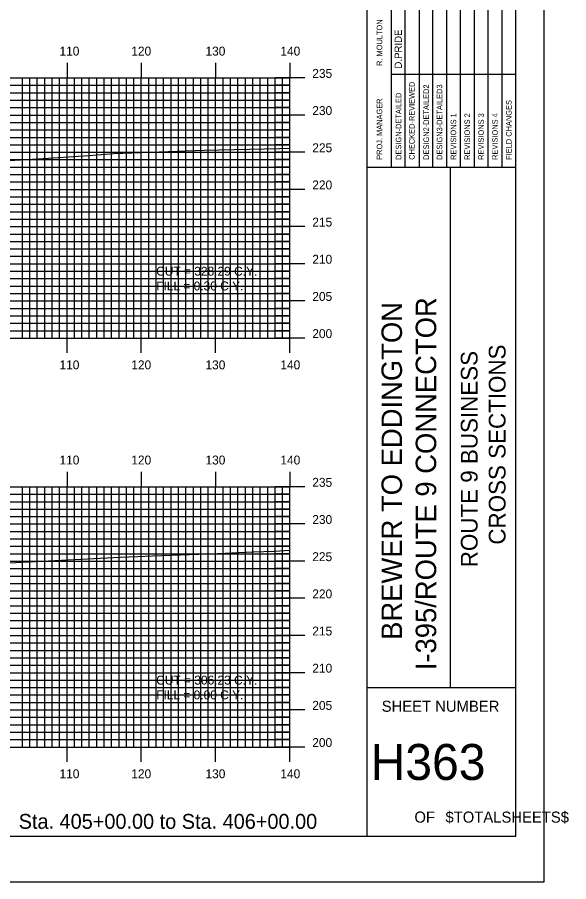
# Model space of a CAD drawing. Extents: x 851742 to 852085, y 364785 to 365005.
# Drawn here: x 852011 to 852085.2, y 364785.1 to 364901.4 of the extents above; entities that cross this region are included whole.
import ezdxf

# ---------------------------------------------------------------- set-up
doc = ezdxf.new("R2010")
doc.units = 0
for name, color, linetype in [('BORDER', 7, 'Continuous'), ('D_Text_Standard', 7, 'Continuous'), ('H_V ANNOTATION', 7, 'Continuous'), ('MAJOR', 7, 'Continuous'), ('MINOR', 7, 'Continuous'), ('PLOT BOUNDARY', 7, 'Continuous'), ('S_Roadway_Centerline', 7, 'Continuous')]:
    doc.layers.add(name, color=color, linetype=linetype)

msp = doc.modelspace()

# ---------------------------------------------------------------- linework, layer by layer
at = {"layer": 'BORDER'}
for p, q in [((852058.1, 364791.23), (852058.1, 365001.23)), ((852058.1, 364881.24), (852078.1, 364881.24)), ((852069.29, 364811.24), (852069.29, 364881.24)), ((852058.1, 364811.24), (852078.1, 364811.24))]:
    msp.add_line(p, q, dxfattribs=at)
msp.add_lwpolyline([(851758.1, 364791.23), (852078.1, 364791.23), (852078.1, 365001.23), (851758.1, 365001.23)], close=True, dxfattribs=at)
for points in [[(852063.2, 364881.24), (852063.2, 364916.24)], [(852065.06, 364916.24), (852065.06, 364881.24)], [(852066.93, 364881.24), (852066.93, 364916.24)], [(852068.79, 364881.24), (852068.79, 364916.24)], [(852070.65, 364881.24), (852070.65, 364916.24)], [(852072.52, 364881.24), (852072.52, 364916.24)], [(852074.38, 364881.24), (852074.38, 364916.24)], [(852076.24, 364881.24), (852076.24, 364916.24)], [(852061.34, 364881.24), (852061.34, 364914.83)], [(852061.33, 364893.74), (852078.1, 364893.74)]]:
    msp.add_lwpolyline(points, dxfattribs=at)
at = {"layer": 'MAJOR'}
for p, q in [((852017.7, 364895.24), (852017.7, 364893.23)), ((852027.7, 364895.24), (852027.7, 364893.23)), ((852037.7, 364895.24), (852037.7, 364893.23)), ((852047.7, 364895.24), (852047.7, 364893.23)), ((851767.7, 364893.23), (852047.7, 364893.23)), ((851767.7, 364893.23), (852047.7, 364893.23)), ((852017.7, 364858.23), (852017.7, 364893.23)), ((852027.7, 364858.23), (852027.7, 364893.23)), ((852037.7, 364858.23), (852037.7, 364893.23)), ((852049.71, 364893.23), (852045.7, 364893.23)), ((852047.7, 364858.23), (852047.7, 364893.23)), ((852047.7, 364858.23), (852047.7, 364893.23)), ((851767.7, 364888.23), (852047.7, 364888.23)), ((852049.71, 364888.23), (852045.7, 364888.23)), ((851767.7, 364883.23), (852047.7, 364883.23)), ((852049.71, 364883.23), (852045.7, 364883.23)), ((851767.7, 364878.23), (852047.7, 364878.23)), ((852049.71, 364878.23), (852045.7, 364878.23)), ((851767.7, 364873.23), (852047.7, 364873.23)), ((852049.71, 364873.23), (852045.7, 364873.23)), ((851767.7, 364868.23), (852047.7, 364868.23)), ((852049.71, 364868.23), (852045.7, 364868.23)), ((851767.7, 364863.23), (852047.7, 364863.23)), ((852049.71, 364863.23), (852045.7, 364863.23)), ((851767.7, 364858.23), (852047.7, 364858.23)), ((851767.7, 364858.23), (852047.7, 364858.23)), ((852017.7, 364856.23), (852017.7, 364858.23)), ((852027.7, 364856.23), (852027.7, 364858.23)), ((852037.7, 364856.23), (852037.7, 364858.23)), ((852049.71, 364858.23), (852045.7, 364858.23)), ((852047.7, 364856.23), (852047.7, 364858.23)), ((852017.7, 364840.24), (852017.7, 364838.23)), ((852027.7, 364840.24), (852027.7, 364838.23)), ((852037.7, 364840.24), (852037.7, 364838.23)), ((852047.7, 364840.24), (852047.7, 364838.23)), ((851767.7, 364838.23), (852047.7, 364838.23)), ((851767.7, 364838.23), (852047.7, 364838.23)), ((852017.7, 364803.23), (852017.7, 364838.23)), ((852027.7, 364803.23), (852027.7, 364838.23)), ((852037.7, 364803.23), (852037.7, 364838.23)), ((852049.71, 364838.23), (852045.7, 364838.23)), ((852047.7, 364803.23), (852047.7, 364838.23)), ((852047.7, 364803.23), (852047.7, 364838.23)), ((851767.7, 364833.23), (852047.7, 364833.23)), ((852049.71, 364833.23), (852045.7, 364833.23)), ((851767.7, 364828.23), (852047.7, 364828.23)), ((852049.71, 364828.23), (852045.7, 364828.23)), ((851767.7, 364823.23), (852047.7, 364823.23)), ((852049.71, 364823.23), (852045.7, 364823.23)), ((851767.7, 364818.23), (852047.7, 364818.23)), ((852049.71, 364818.23), (852045.7, 364818.23)), ((851767.7, 364813.23), (852047.7, 364813.23)), ((852049.71, 364813.23), (852045.7, 364813.23)), ((851767.7, 364808.23), (852047.7, 364808.23)), ((852049.71, 364808.23), (852045.7, 364808.23)), ((851767.7, 364803.23), (852047.7, 364803.23)), ((851767.7, 364803.23), (852047.7, 364803.23)), ((852017.7, 364801.23), (852017.7, 364803.23)), ((852027.7, 364801.23), (852027.7, 364803.23)), ((852037.7, 364801.23), (852037.7, 364803.23)), ((852049.71, 364803.23), (852045.7, 364803.23)), ((852047.7, 364801.23), (852047.7, 364803.23))]:
    msp.add_line(p, q, dxfattribs=at)
at = {"layer": 'MINOR'}
for p, q in [((852011.7, 364858.23), (852011.7, 364893.23)), ((852012.7, 364858.23), (852012.7, 364893.23)), ((852013.7, 364858.23), (852013.7, 364893.23)), ((852014.7, 364858.23), (852014.7, 364893.23)), ((852015.7, 364858.23), (852015.7, 364893.23)), ((852016.7, 364858.23), (852016.7, 364893.23)), ((852018.7, 364858.23), (852018.7, 364893.23)), ((852019.7, 364858.23), (852019.7, 364893.23)), ((852020.7, 364858.23), (852020.7, 364893.23)), ((852021.7, 364858.23), (852021.7, 364893.23)), ((852022.7, 364858.23), (852022.7, 364893.23)), ((852023.7, 364858.23), (852023.7, 364893.23)), ((852024.7, 364858.23), (852024.7, 364893.23)), ((852025.7, 364858.23), (852025.7, 364893.23)), ((852026.7, 364858.23), (852026.7, 364893.23)), ((852028.7, 364858.23), (852028.7, 364893.23)), ((852029.7, 364858.23), (852029.7, 364893.23)), ((852030.7, 364858.23), (852030.7, 364893.23)), ((852031.7, 364858.23), (852031.7, 364893.23)), ((852032.7, 364858.23), (852032.7, 364893.23)), ((852033.7, 364858.23), (852033.7, 364893.23)), ((852034.7, 364858.23), (852034.7, 364893.23)), ((852035.7, 364858.23), (852035.7, 364893.23)), ((852036.7, 364858.23), (852036.7, 364893.23)), ((852038.7, 364858.23), (852038.7, 364893.23)), ((852039.7, 364858.23), (852039.7, 364893.23)), ((852040.7, 364858.23), (852040.7, 364893.23)), ((852041.7, 364858.23), (852041.7, 364893.23)), ((852042.7, 364858.23), (852042.7, 364893.23)), ((852043.7, 364858.23), (852043.7, 364893.23)), ((852044.7, 364858.23), (852044.7, 364893.23)), ((852045.7, 364858.23), (852045.7, 364893.23)), ((852046.7, 364858.23), (852046.7, 364893.23)), ((851767.7, 364892.23), (852047.7, 364892.23)), ((852047.7, 364892.23), (852045.7, 364892.23)), ((851767.7, 364891.23), (852047.7, 364891.23)), ((852047.7, 364891.23), (852045.7, 364891.23)), ((851767.7, 364890.23), (852047.7, 364890.23)), ((852047.7, 364890.23), (852045.7, 364890.23)), ((851767.7, 364889.23), (852047.7, 364889.23)), ((852047.7, 364889.23), (852045.7, 364889.23)), ((851767.7, 364887.23), (852047.7, 364887.23)), ((852047.7, 364887.23), (852045.7, 364887.23)), ((851767.7, 364886.23), (852047.7, 364886.23)), ((852047.7, 364886.23), (852045.7, 364886.23)), ((851767.7, 364885.23), (852047.7, 364885.23)), ((852047.7, 364885.23), (852045.7, 364885.23)), ((851767.7, 364884.23), (852047.7, 364884.23)), ((852047.7, 364884.23), (852045.7, 364884.23)), ((851767.7, 364882.23), (852047.7, 364882.23)), ((851767.7, 364881.23), (852047.7, 364881.23)), ((852047.7, 364882.23), (852045.7, 364882.23)), ((852047.7, 364881.23), (852045.7, 364881.23)), ((851767.7, 364880.23), (852047.7, 364880.23)), ((852047.7, 364880.23), (852045.7, 364880.23)), ((851767.7, 364879.23), (852047.7, 364879.23)), ((852047.7, 364879.23), (852045.7, 364879.23)), ((851767.7, 364877.23), (852047.7, 364877.23)), ((852047.7, 364877.23), (852045.7, 364877.23)), ((851767.7, 364876.23), (852047.7, 364876.23)), ((852047.7, 364876.23), (852045.7, 364876.23)), ((851767.7, 364875.23), (852047.7, 364875.23)), ((851767.7, 364874.23), (852047.7, 364874.23)), ((852047.7, 364875.23), (852045.7, 364875.23)), ((852047.7, 364874.23), (852045.7, 364874.23)), ((851767.7, 364872.23), (852047.7, 364872.23)), ((852047.7, 364872.23), (852045.7, 364872.23)), ((851767.7, 364871.23), (852047.7, 364871.23)), ((852047.7, 364871.23), (852045.7, 364871.23)), ((851767.7, 364870.23), (852047.7, 364870.23)), ((852047.7, 364870.23), (852045.7, 364870.23)), ((851767.7, 364869.23), (852047.7, 364869.23)), ((852047.7, 364869.23), (852045.7, 364869.23)), ((851767.7, 364867.23), (852047.7, 364867.23)), ((852047.7, 364867.23), (852045.7, 364867.23)), ((851767.7, 364866.23), (852047.7, 364866.23)), ((852047.7, 364866.23), (852045.7, 364866.23)), ((851767.7, 364865.23), (852047.7, 364865.23)), ((852047.7, 364865.23), (852045.7, 364865.23)), ((851767.7, 364864.23), (852047.7, 364864.23)), ((852047.7, 364864.23), (852045.7, 364864.23)), ((851767.7, 364862.23), (852047.7, 364862.23)), ((852047.7, 364862.23), (852045.7, 364862.23)), ((851767.7, 364861.23), (852047.7, 364861.23)), ((851767.7, 364860.23), (852047.7, 364860.23)), ((852047.7, 364861.23), (852045.7, 364861.23)), ((852047.7, 364860.23), (852045.7, 364860.23)), ((851767.7, 364859.23), (852047.7, 364859.23)), ((852047.7, 364859.23), (852045.7, 364859.23)), ((852011.7, 364803.23), (852011.7, 364838.23)), ((852012.7, 364803.23), (852012.7, 364838.23)), ((852013.7, 364803.23), (852013.7, 364838.23)), ((852014.7, 364803.23), (852014.7, 364838.23)), ((852015.7, 364803.23), (852015.7, 364838.23)), ((852016.7, 364803.23), (852016.7, 364838.23)), ((852018.7, 364803.23), (852018.7, 364838.23)), ((852019.7, 364803.23), (852019.7, 364838.23)), ((852020.7, 364803.23), (852020.7, 364838.23)), ((852021.7, 364803.23), (852021.7, 364838.23)), ((852022.7, 364803.23), (852022.7, 364838.23)), ((852023.7, 364803.23), (852023.7, 364838.23)), ((852024.7, 364803.23), (852024.7, 364838.23)), ((852025.7, 364803.23), (852025.7, 364838.23)), ((852026.7, 364803.23), (852026.7, 364838.23)), ((852028.7, 364803.23), (852028.7, 364838.23)), ((852029.7, 364803.23), (852029.7, 364838.23)), ((852030.7, 364803.23), (852030.7, 364838.23)), ((852031.7, 364803.23), (852031.7, 364838.23)), ((852032.7, 364803.23), (852032.7, 364838.23)), ((852033.7, 364803.23), (852033.7, 364838.23)), ((852034.7, 364803.23), (852034.7, 364838.23)), ((852035.7, 364803.23), (852035.7, 364838.23)), ((852036.7, 364803.23), (852036.7, 364838.23)), ((852038.7, 364803.23), (852038.7, 364838.23)), ((852039.7, 364803.23), (852039.7, 364838.23)), ((852040.7, 364803.23), (852040.7, 364838.23)), ((852041.7, 364803.23), (852041.7, 364838.23)), ((852042.7, 364803.23), (852042.7, 364838.23)), ((852043.7, 364803.23), (852043.7, 364838.23)), ((852044.7, 364803.23), (852044.7, 364838.23)), ((852045.7, 364803.23), (852045.7, 364838.23)), ((852046.7, 364803.23), (852046.7, 364838.23)), ((851767.7, 364837.23), (852047.7, 364837.23)), ((852047.7, 364837.23), (852045.7, 364837.23)), ((851767.7, 364836.23), (852047.7, 364836.23)), ((852047.7, 364836.23), (852045.7, 364836.23)), ((851767.7, 364835.23), (852047.7, 364835.23)), ((852047.7, 364835.23), (852045.7, 364835.23)), ((851767.7, 364834.23), (852047.7, 364834.23)), ((852047.7, 364834.23), (852045.7, 364834.23)), ((851767.7, 364832.23), (852047.7, 364832.23)), ((851767.7, 364831.23), (852047.7, 364831.23)), ((852047.7, 364832.23), (852045.7, 364832.23)), ((852047.7, 364831.23), (852045.7, 364831.23)), ((851767.7, 364830.23), (852047.7, 364830.23)), ((852047.7, 364830.23), (852045.7, 364830.23)), ((851767.7, 364829.23), (852047.7, 364829.23)), ((852047.7, 364829.23), (852045.7, 364829.23)), ((851767.7, 364827.23), (852047.7, 364827.23)), ((852047.7, 364827.23), (852045.7, 364827.23)), ((851767.7, 364826.23), (852047.7, 364826.23)), ((852047.7, 364826.23), (852045.7, 364826.23)), ((851767.7, 364825.23), (852047.7, 364825.23)), ((851767.7, 364824.23), (852047.7, 364824.23)), ((852047.7, 364825.23), (852045.7, 364825.23)), ((852047.7, 364824.23), (852045.7, 364824.23)), ((851767.7, 364822.23), (852047.7, 364822.23)), ((852047.7, 364822.23), (852045.7, 364822.23)), ((851767.7, 364821.23), (852047.7, 364821.23)), ((852047.7, 364821.23), (852045.7, 364821.23)), ((851767.7, 364820.23), (852047.7, 364820.23)), ((852047.7, 364820.23), (852045.7, 364820.23)), ((851767.7, 364819.23), (852047.7, 364819.23)), ((852047.7, 364819.23), (852045.7, 364819.23)), ((851767.7, 364817.23), (852047.7, 364817.23)), ((852047.7, 364817.23), (852045.7, 364817.23)), ((851767.7, 364816.23), (852047.7, 364816.23)), ((852047.7, 364816.23), (852045.7, 364816.23)), ((851767.7, 364815.23), (852047.7, 364815.23)), ((852047.7, 364815.23), (852045.7, 364815.23)), ((851767.7, 364814.23), (852047.7, 364814.23)), ((852047.7, 364814.23), (852045.7, 364814.23)), ((851767.7, 364812.23), (852047.7, 364812.23)), ((852047.7, 364812.23), (852045.7, 364812.23)), ((851767.7, 364811.23), (852047.7, 364811.23)), ((851767.7, 364810.23), (852047.7, 364810.23)), ((852047.7, 364811.23), (852045.7, 364811.23)), ((852047.7, 364810.23), (852045.7, 364810.23)), ((851767.7, 364809.23), (852047.7, 364809.23)), ((852047.7, 364809.23), (852045.7, 364809.23)), ((851767.7, 364807.23), (852047.7, 364807.23)), ((852047.7, 364807.23), (852045.7, 364807.23)), ((851767.7, 364806.23), (852047.7, 364806.23)), ((852047.7, 364806.23), (852045.7, 364806.23)), ((851767.7, 364805.23), (852047.7, 364805.23)), ((852047.7, 364805.23), (852045.7, 364805.23)), ((851767.7, 364804.23), (852047.7, 364804.23)), ((852047.7, 364804.23), (852045.7, 364804.23))]:
    msp.add_line(p, q, dxfattribs=at)
at = {"layer": 'PLOT BOUNDARY'}
msp.add_lwpolyline([(851741.92, 364785.11), (852081.92, 364785.11), (852081.92, 365005.11), (851741.92, 365005.11)], close=True, dxfattribs=at)
at = {"layer": 'S_Roadway_Centerline'}
for points in [[(851957.38, 364875.53), (851962.41, 364875.74), (851972.95, 364877.92), (851979.66, 364878.84), (851987.06, 364880.07), (852002.38, 364881.62), (852004.16, 364881.69), (852005.24, 364881.86), (852013.79, 364882.32), (852020.64, 364882.8), (852024.01, 364883.07), (852036.16, 364883.49), (852046.27, 364883.75), (852047.7, 364883.79)], [(852009.91, 364827.99), (852024.86, 364828.78), (852027.19, 364828.87), (852029.22, 364828.93), (852037.94, 364829.25), (852038.06, 364829.28), (852040.83, 364829.38), (852042.81, 364829.47), (852045.56, 364829.59), (852047.7, 364829.7)]]:
    msp.add_lwpolyline(points, dxfattribs=at)

# ---------------------------------------------------------------- texts
at = {"layer": 'BORDER'}
for s, height, p in [('R. MOULTON', 0.745, (852060.11, 364894.84)), ('D.PRIDE', 0.969, (852062.75, 364894.48)), ('CHECKED-REVIEWED', 0.7455, (852064.47, 364882.21)), ('DESIGN2-DETAILED2', 0.7455, (852066.4, 364882.21)), ('DESIGN3-DETAILED3', 0.7455, (852068.19, 364882.21)), ('PROJ. MANAGER', 0.7455, (852060.11, 364882.21)), ('DESIGN-DETAILED', 0.7455, (852062.68, 364882.21)), ('FIELD CHANGES', 0.7455, (852077.51, 364882.21)), ('REVISIONS 1', 0.7455, (852070.06, 364882.21)), ('REVISIONS 2', 0.7455, (852071.92, 364882.21)), ('REVISIONS 3', 0.7455, (852073.78, 364882.21)), ('REVISIONS 4', 0.7455, (852075.65, 364882.21)), ('BREWER TO EDDINGTON', 2.7557, (852062.77, 364817.64)), ('I-395/ROUTE 9 CONNECTOR', 2.7557, (852067.37, 364813.56)), ('CROSS SECTIONS', 2.25, (852076.7, 364830.45)), ('ROUTE 9 BUSINESS', 2.25, (852072.94, 364827.41))]:
    msp.add_text(s, height=height, rotation=90, dxfattribs=at).set_placement(p)
for s, height, p in [('SHEET NUMBER', 1.4905, (852060.04, 364807.97)), ('H363', 4.839, (852058.54, 364798.8)), ('OF', 1.491, (852064.44, 364793.06)), ('$TOTALSHEETS$', 1.4905, (852068.62, 364793.06))]:
    msp.add_text(s, height=height, dxfattribs=at).set_placement(p)
at = {"layer": 'D_Text_Standard'}
for s, p in [('CUT = 328.29 C.Y.', (852029.7, 364866.63)), ('FILL = 0.30 C.Y.', (852029.7, 364864.64)), ('CUT = 306.23 C.Y.', (852029.7, 364811.63)), ('FILL = 0.00 C.Y.', (852029.7, 364809.64))]:
    msp.add_text(s, height=1.2, dxfattribs=at).set_placement(p)
at = {"layer": 'H_V ANNOTATION'}
for s, height, p in [('110', 1.2, (852016.69, 364896.23)), ('120', 1.2, (852026.35, 364896.23)), ('130', 1.2, (852036.33, 364896.23)), ('140', 1.2, (852046.41, 364896.23)), ('235', 1.2, (852050.7, 364893.23)), ('230', 1.2, (852050.7, 364888.23)), ('225', 1.2, (852050.7, 364883.23)), ('220', 1.2, (852050.7, 364878.23)), ('215', 1.2, (852050.7, 364873.23)), ('210', 1.2, (852050.7, 364868.23)), ('205', 1.2, (852050.7, 364863.23)), ('200', 1.2, (852050.7, 364858.23)), ('110', 1.2, (852016.69, 364854.03)), ('120', 1.2, (852026.35, 364854.03)), ('130', 1.2, (852036.33, 364854.03)), ('140', 1.2, (852046.41, 364854.03)), ('110', 1.2, (852016.69, 364841.23)), ('120', 1.2, (852026.35, 364841.23)), ('130', 1.2, (852036.33, 364841.23)), ('140', 1.2, (852046.41, 364841.23)), ('235', 1.2, (852050.7, 364838.23)), ('230', 1.2, (852050.7, 364833.23)), ('225', 1.2, (852050.7, 364828.23)), ('220', 1.2, (852050.7, 364823.23)), ('215', 1.2, (852050.7, 364818.23)), ('210', 1.2, (852050.7, 364813.23)), ('205', 1.2, (852050.7, 364808.23)), ('200', 1.2, (852050.7, 364803.23)), ('110', 1.2, (852016.69, 364799.03)), ('120', 1.2, (852026.35, 364799.03)), ('130', 1.2, (852036.33, 364799.03)), ('140', 1.2, (852046.41, 364799.03)), ('Sta. 405+00.00 to Sta. 406+00.00', 2.0004, (852011.2, 364792.23))]:
    msp.add_text(s, height=height, dxfattribs=at).set_placement(p)

doc.saveas('drawing.dxf')
